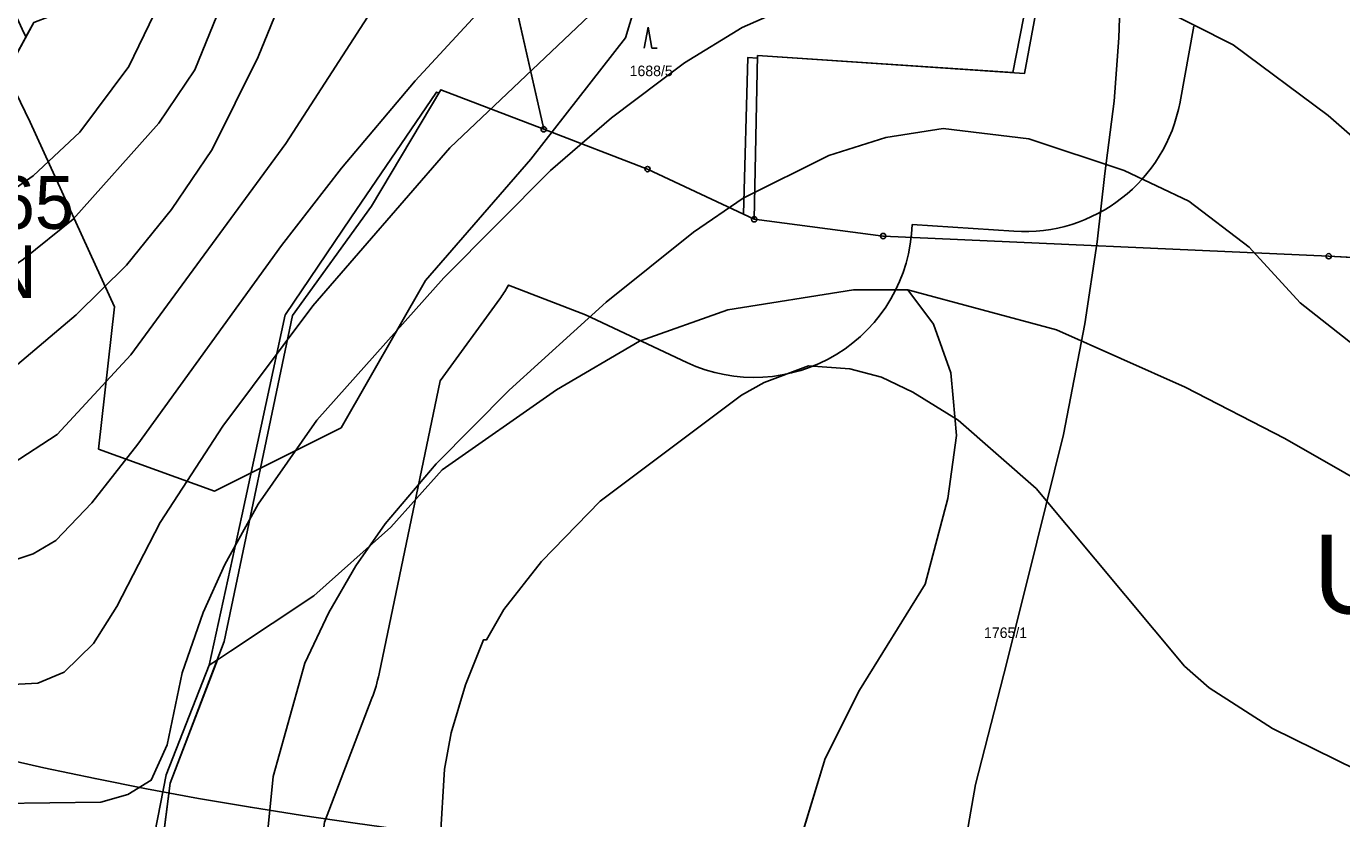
# Model space of a CAD drawing. Extents: x -706130 to -698555, y -971544 to -967260.
# Drawn here: x -704339.7 to -704090.1, y -970570.1 to -970419.8 of the extents above; entities that cross this region are included whole.
import ezdxf

# ---------------------------------------------------------------- set-up
doc = ezdxf.new("R2010")
doc.units = 0
for name, color, linetype in [('BPEJ hranice S', 7, 'Continuous'), ('BPEJ I-II trida ochrany S', 7, 'Continuous'), ('Docházková izochrona - VLAK N', 7, 'Continuous'), ('KN_Hranice_parcel', 7, 'Continuous'), ('KN_Parcelni cisla', 7, 'Continuous'), ('KN_Polygon parcely', 7, 'Continuous'), ('KN_Popisy_pomistni nazvy', 7, 'Continuous'), ('KN_POZEMKY_10_LESNI POZEMEK', 7, 'Continuous'), ('KN_POZEMKY_2_ORNA PUDA', 7, 'Continuous'), ('KN_POZEMKY_7_TTP', 7, 'Continuous'), ('KN_Značky bodu BP', 7, 'Continuous'), ('KN_Značky kultur', 7, 'Continuous'), ('OP lesa 30 m', 7, 'Continuous'), ('Plochy lesní všeobecné S', 7, 'Continuous'), ('Plochy smíšené nezastavěného území všeobecné S', 7, 'Continuous'), ('Plochy zemědělské všeobecné CELEK S', 7, 'Continuous'), ('Regulační bloky v krajině S', 7, 'Continuous'), ('Regulační kódy v krajině S', 7, 'Continuous'), ('Regulační kódy zastavěné S', 7, 'Continuous'), ('Sesuvné území S', 7, 'Continuous'), ('Spoje_dálkový komunikační kabel S', 7, 'Continuous'), ('VÝŠKOPIS_vrstevnice hlavní', 7, 'Continuous'), ('VÝŠKOPIS_vrstevnice zesílená', 7, 'Continuous')]:
    doc.layers.add(name, color=color, linetype=linetype)

msp = doc.modelspace()

# ---------------------------------------------------------------- linework, layer by layer
at = {"layer": 'BPEJ hranice S'}
for points in [[(-704338.52, -970419.53), (-704339.79, -970421.83), (-704340.49, -970420.33), (-704347.35, -970405.44)], [(-704318, -970586.4), (-704313.18, -970561.79), (-704305.04, -970541.03), (-704298.85, -970512.7), (-704290.57, -970474.54), (-704290.53, -970474.47), (-704278.11, -970456.17), (-704261.9, -970432.27), (-704261.45, -970432.46), (-704261.09, -970431.85), (-704241.54, -970439.34), (-704221.84, -970446.9), (-704203.62, -970455.47), (-704202.79, -970425.72), (-704200.97, -970425.85), (-704200.96, -970425.35), (-704152.56, -970428.59), (-704149.79, -970414.64)], [(-704078.13, -970511.01), (-704100.89, -970498), (-704119.86, -970488.24), (-704144.25, -970477.4), (-704172.44, -970469.8), (-704182.74, -970469.8), (-704206.59, -970473.6), (-704223.39, -970479.56), (-704239.11, -970488.78), (-704260.79, -970503.97), (-704270.55, -970514.81), (-704285.18, -970527.82), (-704300.96, -970538.32), (-704303.47, -970539.98), (-704305.04, -970541.03), (-704298.85, -970512.7), (-704290.57, -970474.54), (-704290.53, -970474.47), (-704278.11, -970456.17), (-704261.9, -970432.27), (-704261.45, -970432.46), (-704261.09, -970431.85), (-704241.54, -970439.34), (-704221.84, -970446.9), (-704203.62, -970455.47), (-704202.79, -970425.72), (-704200.97, -970425.85), (-704200.96, -970425.35), (-704152.56, -970428.59), (-704149.79, -970414.64)], [(-704338.52, -970419.53), (-704339.79, -970421.83)], [(-704318, -970586.4), (-704313.18, -970561.79), (-704305.04, -970541.03), (-704303.47, -970539.98), (-704300.96, -970538.32), (-704285.18, -970527.82), (-704270.55, -970514.81), (-704260.79, -970503.97), (-704239.11, -970488.78), (-704223.39, -970479.56), (-704206.59, -970473.6), (-704182.74, -970469.8), (-704172.44, -970469.8), (-704167.56, -970476.31), (-704164.31, -970485.53), (-704163.87, -970490.35), (-704163.22, -970497.46), (-704164.85, -970509.39), (-704169.19, -970525.66), (-704181.65, -970545.72), (-704188.16, -970558.73), (-704193.44, -970576.08)], [(-704246.16, -970725.33), (-704211.33, -970681.82), (-704203.61, -970665.67), (-704199.41, -970656.88), (-704193.98, -970625.43), (-704193.17, -970613.49), (-704192.36, -970601.57), (-704193.44, -970576.08), (-704188.16, -970558.73), (-704181.65, -970545.72), (-704169.19, -970525.66), (-704164.85, -970509.39), (-704163.22, -970497.46), (-704163.87, -970490.35), (-704164.31, -970485.53), (-704167.56, -970476.31), (-704172.44, -970469.8), (-704144.25, -970477.4), (-704119.86, -970488.24), (-704100.89, -970498), (-704078.13, -970511.01)]]:
    msp.add_lwpolyline(points, dxfattribs=at)
at = {"layer": 'BPEJ I-II trida ochrany S'}
for p, q in [((-704163.22, -970497.46), (-704163.87, -970490.35)), ((-704260.79, -970503.97), (-704270.55, -970514.81)), ((-704270.55, -970514.81), (-704285.18, -970527.82)), ((-704181.65, -970545.72), (-704169.19, -970525.66)), ((-704285.18, -970527.82), (-704300.96, -970538.32)), ((-704300.96, -970538.32), (-704303.47, -970539.98)), ((-704303.47, -970539.98), (-704312.43, -970563.41)), ((-704188.16, -970558.73), (-704181.65, -970545.72)), ((-704193.44, -970576.08), (-704188.16, -970558.73)), ((-704312.43, -970563.41), (-704315.52, -970587.47))]:
    msp.add_line(p, q, dxfattribs=at)
for points in [[(-704163.87, -970490.35), (-704164.31, -970485.53), (-704167.56, -970476.31), (-704172.44, -970469.8), (-704182.74, -970469.8), (-704206.59, -970473.6), (-704223.39, -970479.56)], [(-704223.39, -970479.56), (-704239.11, -970488.78), (-704260.79, -970503.97)], [(-704169.19, -970525.66), (-704164.85, -970509.39), (-704163.22, -970497.46)]]:
    msp.add_lwpolyline(points, dxfattribs=at)
at = {"layer": 'Docházková izochrona - VLAK N'}
msp.add_circle((-704165.45, -969778.77), 800, dxfattribs=at)
at = {"layer": 'KN_Hranice_parcel'}
msp.add_line((-704241.54, -970439.34), (-704255.48, -970377.7), dxfattribs=at)
for points in [[(-704351.28, -970442.67), (-704338.27, -970419.08), (-704314.53, -970409.91)], [(-704201.61, -970456.42), (-704200.96, -970425.35), (-704150.31, -970428.74), (-704147.67, -970414.38)], [(-704315.52, -970587.47), (-704312.43, -970563.41), (-704302.15, -970536.53), (-704289.23, -970474.65), (-704274.19, -970453.9), (-704261.09, -970431.85), (-704241.54, -970439.34)], [(-704241.54, -970439.34), (-704221.84, -970446.9), (-704201.61, -970456.42)], [(-704047.91, -970462.01), (-704081.65, -970464.04), (-704092.6, -970463.42), (-704177.13, -970459.6), (-704201.61, -970456.42)]]:
    msp.add_lwpolyline(points, dxfattribs=at)
at = {"layer": 'KN_Polygon parcely'}
for points in [[(-704054.81, -970362.83), (-704083.98, -970360.18), (-704125.78, -970355.06), (-704175.54, -970351.17), (-704263.51, -970345.81), (-704260.19, -970378.07), (-704255.48, -970377.7), (-704227.73, -970383.43), (-704220.8, -970382.6), (-704221.32, -970406.23), (-704160.16, -970413), (-704151.46, -970405.74), (-704118.52, -970411.14), (-704145.56, -970412.88), (-704147.67, -970414.38), (-704150.31, -970428.74), (-704200.96, -970425.35), (-704201.61, -970456.42), (-704177.13, -970459.6), (-704092.6, -970463.42), (-704081.65, -970464.04), (-704047.91, -970462.01)], [(-704221.84, -970446.9), (-704201.61, -970456.42), (-704200.96, -970425.35), (-704150.31, -970428.74), (-704147.67, -970414.38), (-704160.16, -970413), (-704221.32, -970406.23), (-704220.8, -970382.6), (-704227.73, -970383.43), (-704255.48, -970377.7), (-704241.54, -970439.34)], [(-704377.15, -970424.22), (-704351.28, -970442.67), (-704338.27, -970419.08), (-704314.53, -970409.91), (-704347.89, -970396.42), (-704349.12, -970414.28), (-704381.94, -970403.15), (-704386.46, -970409.76), (-704394.69, -970423.1), (-704385.61, -970432.84)], [(-704177.13, -970459.6), (-704201.61, -970456.42), (-704221.84, -970446.9), (-704241.54, -970439.34), (-704261.09, -970431.85), (-704274.19, -970453.9), (-704289.23, -970474.65), (-704302.15, -970536.53), (-704312.43, -970563.41), (-704315.52, -970587.47), (-704232.28, -970609.54), (-704191.1, -970613.7), (-704175.4, -970615.17), (-704145.88, -970618.09), (-704124.32, -970620.81), (-704098.61, -970623.43), (-704029.48, -970627.05), (-704024.67, -970626.33), (-704033.69, -970572.84), (-704021.52, -970457.99), (-704047.91, -970462.01), (-704081.65, -970464.04), (-704092.6, -970463.42)]]:
    msp.add_lwpolyline(points, close=True, dxfattribs=at)
for points in [[(-704314.41, -970716.03), (-704304.49, -970694.37), (-704315.1, -970655.91), (-704326.45, -970652.69), (-704339.15, -970594), (-704337.78, -970577.91), (-704315.52, -970587.47), (-704312.43, -970563.41), (-704302.15, -970536.53), (-704289.23, -970474.65), (-704274.19, -970453.9), (-704261.09, -970431.85), (-704241.54, -970439.34), (-704255.48, -970377.7)], [(-704338.27, -970419.08), (-704351.28, -970442.67), (-704352.57, -970444.4), (-704352.11, -970446.17), (-704347.68, -970463.22), (-704349.74, -970487.8), (-704373.16, -970465.99), (-704375.18, -970464.11), (-704380.05, -970468.36), (-704382.69, -970470.66), (-704386.37, -970466.71), (-704410.26, -970471.29), (-704429.88, -970483.99), (-704437.86, -970500.93), (-704440.81, -970512.35), (-704444.18, -970537.3), (-704437.59, -970564.83), (-704389.48, -970641.61), (-704384.25, -970653.17), (-704379.8, -970666.04), (-704377.6, -970678.33), (-704377.41, -970702.19), (-704385.12, -970737.85)]]:
    msp.add_lwpolyline(points, dxfattribs=at)
at = {"layer": 'KN_POZEMKY_10_LESNI POZEMEK'}
for p, q in [((-704241.54, -970439.34), (-704255.48, -970377.7)), ((-704255.48, -970377.7), (-704241.54, -970439.34)), ((-704147.67, -970414.38), (-704150.31, -970428.74)), ((-704351.28, -970442.67), (-704338.27, -970419.08)), ((-704200.96, -970425.35), (-704201.61, -970456.42)), ((-704150.31, -970428.74), (-704200.96, -970425.35)), ((-704261.09, -970431.85), (-704274.19, -970453.9)), ((-704241.54, -970439.34), (-704261.09, -970431.85)), ((-704221.84, -970446.9), (-704241.54, -970439.34)), ((-704201.61, -970456.42), (-704221.84, -970446.9)), ((-704274.19, -970453.9), (-704289.23, -970474.65)), ((-704289.23, -970474.65), (-704302.15, -970536.53)), ((-704302.15, -970536.53), (-704312.43, -970563.41)), ((-704312.43, -970563.41), (-704315.52, -970587.47))]:
    msp.add_line(p, q, dxfattribs=at)
at = {"layer": 'KN_POZEMKY_2_ORNA PUDA'}
for p, q in [((-704274.19, -970453.9), (-704261.09, -970431.85)), ((-704261.09, -970431.85), (-704241.54, -970439.34)), ((-704241.54, -970439.34), (-704221.84, -970446.9)), ((-704221.84, -970446.9), (-704201.61, -970456.42)), ((-704289.23, -970474.65), (-704274.19, -970453.9)), ((-704201.61, -970456.42), (-704177.13, -970459.6)), ((-704177.13, -970459.6), (-704092.6, -970463.42)), ((-704092.6, -970463.42), (-704081.65, -970464.04)), ((-704302.15, -970536.53), (-704289.23, -970474.65)), ((-704312.43, -970563.41), (-704302.15, -970536.53)), ((-704315.52, -970587.47), (-704312.43, -970563.41))]:
    msp.add_line(p, q, dxfattribs=at)
at = {"layer": 'KN_POZEMKY_7_TTP'}
for p, q in [((-704150.31, -970428.74), (-704147.67, -970414.38)), ((-704338.27, -970419.08), (-704351.28, -970442.67)), ((-704201.61, -970456.42), (-704200.96, -970425.35)), ((-704200.96, -970425.35), (-704150.31, -970428.74)), ((-704177.13, -970459.6), (-704201.61, -970456.42)), ((-704092.6, -970463.42), (-704177.13, -970459.6)), ((-704081.65, -970464.04), (-704092.6, -970463.42))]:
    msp.add_line(p, q, dxfattribs=at)
at = {"layer": 'KN_Značky bodu BP'}
for centre, radius in [((-704241.54, -970439.34), 0.5), ((-704241.54, -970439.34), 0.0303), ((-704221.84, -970446.9), 0.5), ((-704221.84, -970446.9), 0.0303), ((-704201.61, -970456.42), 0.5), ((-704201.61, -970456.42), 0.0303), ((-704177.13, -970459.6), 0.5), ((-704177.13, -970459.6), 0.0303), ((-704092.6, -970463.42), 0.5), ((-704092.6, -970463.42), 0.0303)]:
    msp.add_circle(centre, radius, dxfattribs=at)
at = {"layer": 'KN_Značky kultur'}
for p, q in [((-704221.75, -970419.98), (-704222.5, -970423.98)), ((-704221, -970423.98), (-704221.75, -970419.98)), ((-704221, -970423.98), (-704220, -970423.98))]:
    msp.add_line(p, q, dxfattribs=at)
at = {"layer": 'OP lesa 30 m'}
for p, q in [((-704120.8, -970434.16), (-704118.16, -970419.8)), ((-704171.63, -970457.38), (-704152.31, -970458.67))]:
    msp.add_line(p, q, dxfattribs=at)
for points in [[(-704248.4, -970469.22), (-704248.21, -970468.91), (-704233.62, -970474.51), (-704214.38, -970483.56)], [(-704272.78, -970542.66), (-704261.17, -970487.06), (-704249.9, -970471.51)], [(-704285.76, -970591.29), (-704283.13, -970570.78), (-704274.13, -970547.25)]]:
    msp.add_lwpolyline(points, dxfattribs=at)
for centre, start, end in [((-704150.31, -970428.74), 266.1709, 349.5828), ((-704201.61, -970456.42), 244.7989, 358.1653), ((-704274.19, -970453.9), 324.0647, 329.2853), ((-704302.15, -970536.53), 339.0711, 348.2066)]:
    msp.add_arc(centre, 30, start, end, dxfattribs=at)
at = {"layer": 'Plochy lesní všeobecné S'}
for p, q in [((-704150.31, -970428.74), (-704147.67, -970414.38)), ((-704338.27, -970419.08), (-704351.28, -970442.67)), ((-704201.61, -970456.42), (-704200.96, -970425.35)), ((-704200.96, -970425.35), (-704150.31, -970428.74)), ((-704274.19, -970453.9), (-704261.09, -970431.85)), ((-704261.09, -970431.85), (-704241.54, -970439.34)), ((-704241.54, -970439.34), (-704221.84, -970446.9)), ((-704221.84, -970446.9), (-704201.61, -970456.42)), ((-704289.23, -970474.65), (-704274.19, -970453.9)), ((-704302.15, -970536.53), (-704289.23, -970474.65)), ((-704312.43, -970563.41), (-704302.15, -970536.53)), ((-704315.52, -970587.47), (-704312.43, -970563.41))]:
    msp.add_line(p, q, dxfattribs=at)
at = {"layer": 'Plochy smíšené nezastavěného území všeobecné S'}
msp.add_lwpolyline([(-704351.28, -970442.67), (-704338.27, -970419.08), (-704314.53, -970409.91)], dxfattribs=at)
at = {"layer": 'Plochy zemědělské všeobecné CELEK S'}
for p, q in [((-704147.67, -970414.38), (-704150.31, -970428.74)), ((-704261.09, -970431.85), (-704274.19, -970453.9)), ((-704241.54, -970439.34), (-704261.09, -970431.85)), ((-704221.84, -970446.9), (-704241.54, -970439.34)), ((-704201.61, -970456.42), (-704221.84, -970446.9)), ((-704274.19, -970453.9), (-704289.23, -970474.65)), ((-704289.23, -970474.65), (-704302.15, -970536.53)), ((-704302.15, -970536.53), (-704312.43, -970563.41)), ((-704312.43, -970563.41), (-704315.52, -970587.47))]:
    msp.add_line(p, q, dxfattribs=at)
msp.add_lwpolyline([(-704150.31, -970428.74), (-704200.96, -970425.35), (-704201.61, -970456.42)], dxfattribs=at)
at = {"layer": 'Regulační bloky v krajině S'}
for p, q in [((-704150.31, -970428.74), (-704147.67, -970414.38)), ((-704147.67, -970414.38), (-704150.31, -970428.74)), ((-704338.27, -970419.08), (-704351.28, -970442.67)), ((-704201.61, -970456.42), (-704200.96, -970425.35)), ((-704200.96, -970425.35), (-704150.31, -970428.74)), ((-704274.19, -970453.9), (-704261.09, -970431.85)), ((-704261.09, -970431.85), (-704274.19, -970453.9)), ((-704261.09, -970431.85), (-704241.54, -970439.34)), ((-704241.54, -970439.34), (-704261.09, -970431.85)), ((-704241.54, -970439.34), (-704221.84, -970446.9)), ((-704221.84, -970446.9), (-704241.54, -970439.34)), ((-704221.84, -970446.9), (-704201.61, -970456.42)), ((-704201.61, -970456.42), (-704221.84, -970446.9)), ((-704289.23, -970474.65), (-704274.19, -970453.9)), ((-704274.19, -970453.9), (-704289.23, -970474.65)), ((-704302.15, -970536.53), (-704289.23, -970474.65)), ((-704289.23, -970474.65), (-704302.15, -970536.53)), ((-704312.43, -970563.41), (-704302.15, -970536.53)), ((-704302.15, -970536.53), (-704312.43, -970563.41)), ((-704315.52, -970587.47), (-704312.43, -970563.41)), ((-704312.43, -970563.41), (-704315.52, -970587.47))]:
    msp.add_line(p, q, dxfattribs=at)
for points in [[(-704351.28, -970442.67), (-704338.27, -970419.08), (-704314.53, -970409.91)], [(-704150.31, -970428.74), (-704200.96, -970425.35), (-704201.61, -970456.42)]]:
    msp.add_lwpolyline(points, dxfattribs=at)
at = {"layer": 'Sesuvné území S'}
msp.add_lwpolyline([(-704057, -970260), (-704100, -970255), (-704164, -970242), (-704198, -970251), (-704225, -970268), (-704245, -970291), (-704266, -970316), (-704300, -970350), (-704343, -970385), (-704353, -970409), (-704339, -970438), (-704323, -970473), (-704326, -970500), (-704304, -970508), (-704280, -970496), (-704264, -970468), (-704244, -970445), (-704226, -970422), (-704217, -970392), (-704180, -970359), (-704170, -970353), (-704150, -970340), (-704080, -970303)], dxfattribs=at)
at = {"layer": 'Spoje_dálkový komunikační kabel S'}
msp.add_lwpolyline([(-704132.1, -970412.49), (-704132.43, -970422.02), (-704133.28, -970434.03), (-704135.07, -970447.72), (-704136.52, -970460.68), (-704138.88, -970476.22), (-704142.94, -970497.27), (-704147.98, -970517.7), (-704153.66, -970540.48), (-704159.6, -970563.67), (-704163.47, -970585.72), (-704167.61, -970606.24), (-704171.94, -970629.46), (-704175.58, -970650.33), (-704179.58, -970671.17), (-704183.25, -970691.26), (-704187.74, -970712.76)], dxfattribs=at)
at = {"layer": 'VÝŠKOPIS_vrstevnice hlavní'}
for points in [[(-704282.62, -970342.86), (-704287.47, -970352.41), (-704290.89, -970362.4), (-704294.74, -970379.38), (-704297.46, -970396.36), (-704302.16, -970414.33), (-704307.73, -970428.03), (-704314.58, -970438.16), (-704330.84, -970456.42), (-704340.26, -970463.98), (-704353.38, -970472.97), (-704397.75, -970491.52), (-704409.03, -970498.37), (-704415.73, -970503.79), (-704425, -970513.63), (-704431.14, -970523.33), (-704433.56, -970531.89), (-704436.7, -970546.87), (-704443.1, -970548.22)], [(-704259.51, -970394.07), (-704290.47, -970442.01), (-704319.86, -970482.1), (-704333.84, -970497.22), (-704342.4, -970502.79), (-704368.93, -970512.21), (-704383.34, -970519.77), (-704391.19, -970525.62), (-704398.47, -970533.61), (-704402.75, -970540.45), (-704405.89, -970549.59), (-704407.03, -970556.43), (-704406.88, -970565.56), (-704405.74, -970571.84), (-704402.18, -970581.83), (-704387.91, -970610.65), (-704378.92, -970632.62), (-704375.21, -970644.6), (-704372.79, -970656.59), (-704372.64, -970668.57), (-704375.71, -970676.18), (-704379.34, -970678.96), (-704384.89, -970678.53), (-704388.52, -970687.29)], [(-704241.1, -970403.21), (-704265.93, -970430.17), (-704279.91, -970446.72), (-704291.32, -970461.41), (-704318.57, -970499.08), (-704327.28, -970510.21), (-704334.12, -970517.34), (-704338.4, -970519.91), (-704343.54, -970521.62)], [(-704186.89, -970412.48), (-704203.86, -970420.04), (-704214.85, -970426.75), (-704228.69, -970437.16), (-704240.24, -970447.15), (-704260.51, -970467.55), (-704284.62, -970494.51), (-704295.74, -970510.49), (-704302.02, -970521.91), (-704306.16, -970531.04), (-704310.15, -970542.45), (-704313.01, -970556.15), (-704316, -970562.85), (-704320.43, -970565.56), (-704325.56, -970566.99), (-704344.97, -970567.28)], [(-704084.02, -970444.29), (-704092.72, -970436.73), (-704110.7, -970423.32), (-704132.67, -970412.19)], [(-704232.83, -970417.76), (-704259.36, -970442.87), (-704285.33, -970472.83), (-704302.45, -970495.66), (-704314.29, -970513.92), (-704322.57, -970529.9), (-704326.99, -970536.89), (-704332.55, -970542.31), (-704337.55, -970544.45), (-704362.66, -970545.73), (-704370.36, -970548.44), (-704376.07, -970554.44), (-704379.78, -970561.28), (-704381.63, -970570.99), (-704380.49, -970577.83), (-704378.21, -970584.68), (-704369.36, -970600.66), (-704356.52, -970630.34), (-704348.96, -970655.45), (-704346.82, -970666.86), (-704346.11, -970687.41), (-704349.1, -970701.1), (-704357.81, -970721.65)], [(-704315.43, -970417.47), (-704320.28, -970427.46), (-704329.56, -970439.87), (-704338.4, -970448.15), (-704342.2, -970450.85)], [(-704087.3, -970560.86), (-704103.28, -970553.01), (-704115.27, -970545.31), (-704119.97, -970541.17), (-704148.08, -970507.5), (-704162.92, -970494.51), (-704171.48, -970489.24), (-704177.47, -970486.38), (-704183.46, -970484.81), (-704191.31, -970484.24), (-704199.73, -970487.38), (-704204.01, -970489.81), (-704230.83, -970509.92), (-704241.96, -970521.34), (-704249.09, -970530.47), (-704252.37, -970536.17), (-704252.94, -970536.17), (-704256.37, -970544.73), (-704259.08, -970553.87), (-704260.36, -970560.71), (-704261.22, -970574.41)]]:
    msp.add_lwpolyline(points, dxfattribs=at)
at = {"layer": 'VÝŠKOPIS_vrstevnice zesílená'}
for points in [[(-704232.39, -970347.11), (-704252.41, -970354.57), (-704265.49, -970364.44), (-704273.2, -970373.53), (-704280.62, -970388.51), (-704295.74, -970425.6), (-704304.45, -970443.15), (-704312.15, -970454.57), (-704320.71, -970465.12), (-704330.27, -970474.54), (-704341.4, -970483.96), (-704360.09, -970494.37), (-704381.49, -970503.36), (-704391.33, -970508.5), (-704404.46, -970518.2), (-704407.74, -970522.05), (-704413.02, -970531.18), (-704415.87, -970537.6), (-704419.01, -970551.01), (-704418.58, -970562.43), (-704417.16, -970572.7), (-704410.74, -970593.24), (-704408.74, -970601.8), (-704414.15, -970606.55)], [(-704087.87, -970480.25), (-704098, -970472.26), (-704107.7, -970461.7), (-704119.12, -970453), (-704131.39, -970447.15), (-704149.51, -970441.16), (-704165.77, -970439.16), (-704176.61, -970440.87), (-704187.46, -970444.29), (-704203.72, -970452.43), (-704213.14, -970458.85), (-704229.69, -970472.11), (-704248.09, -970488.81), (-704261.93, -970502.79), (-704271.63, -970514.2), (-704277.2, -970522.19), (-704282.33, -970531.04), (-704286.9, -970540.6), (-704292.89, -970562.14), (-704294.6, -970579.26)]]:
    msp.add_lwpolyline(points, dxfattribs=at)

# ---------------------------------------------------------------- texts
at = {"layer": 'KN_Parcelni cisla'}
for s, p in [('1688/5', (-704225.24, -970429.26)), ('1765/1', (-704158, -970535.85))]:
    msp.add_text(s, height=2, dxfattribs=at).set_placement(p)
at = {"layer": 'KN_Popisy_pomistni nazvy'}
msp.add_text('U jasanu', height=15, dxfattribs=at).set_placement((-704095.46, -970531.25))
at = {"layer": 'Regulační kódy v krajině S'}
msp.add_text('MN', height=10, dxfattribs=at).set_placement((-704358.56, -970471.36))
at = {"layer": 'Regulační kódy zastavěné S'}
msp.add_text('SV.1.18.65', height=10, dxfattribs=at).set_placement((-704396.83, -970458.23))

doc.saveas('drawing.dxf')
